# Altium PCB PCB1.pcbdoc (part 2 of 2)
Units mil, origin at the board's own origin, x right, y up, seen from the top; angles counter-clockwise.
Board outline 7352.2 x 4397.09 mil, 2 copper layers (Top Layer, Bottom Layer); 16 components, 5 nets, 164 pads, 4 vias.
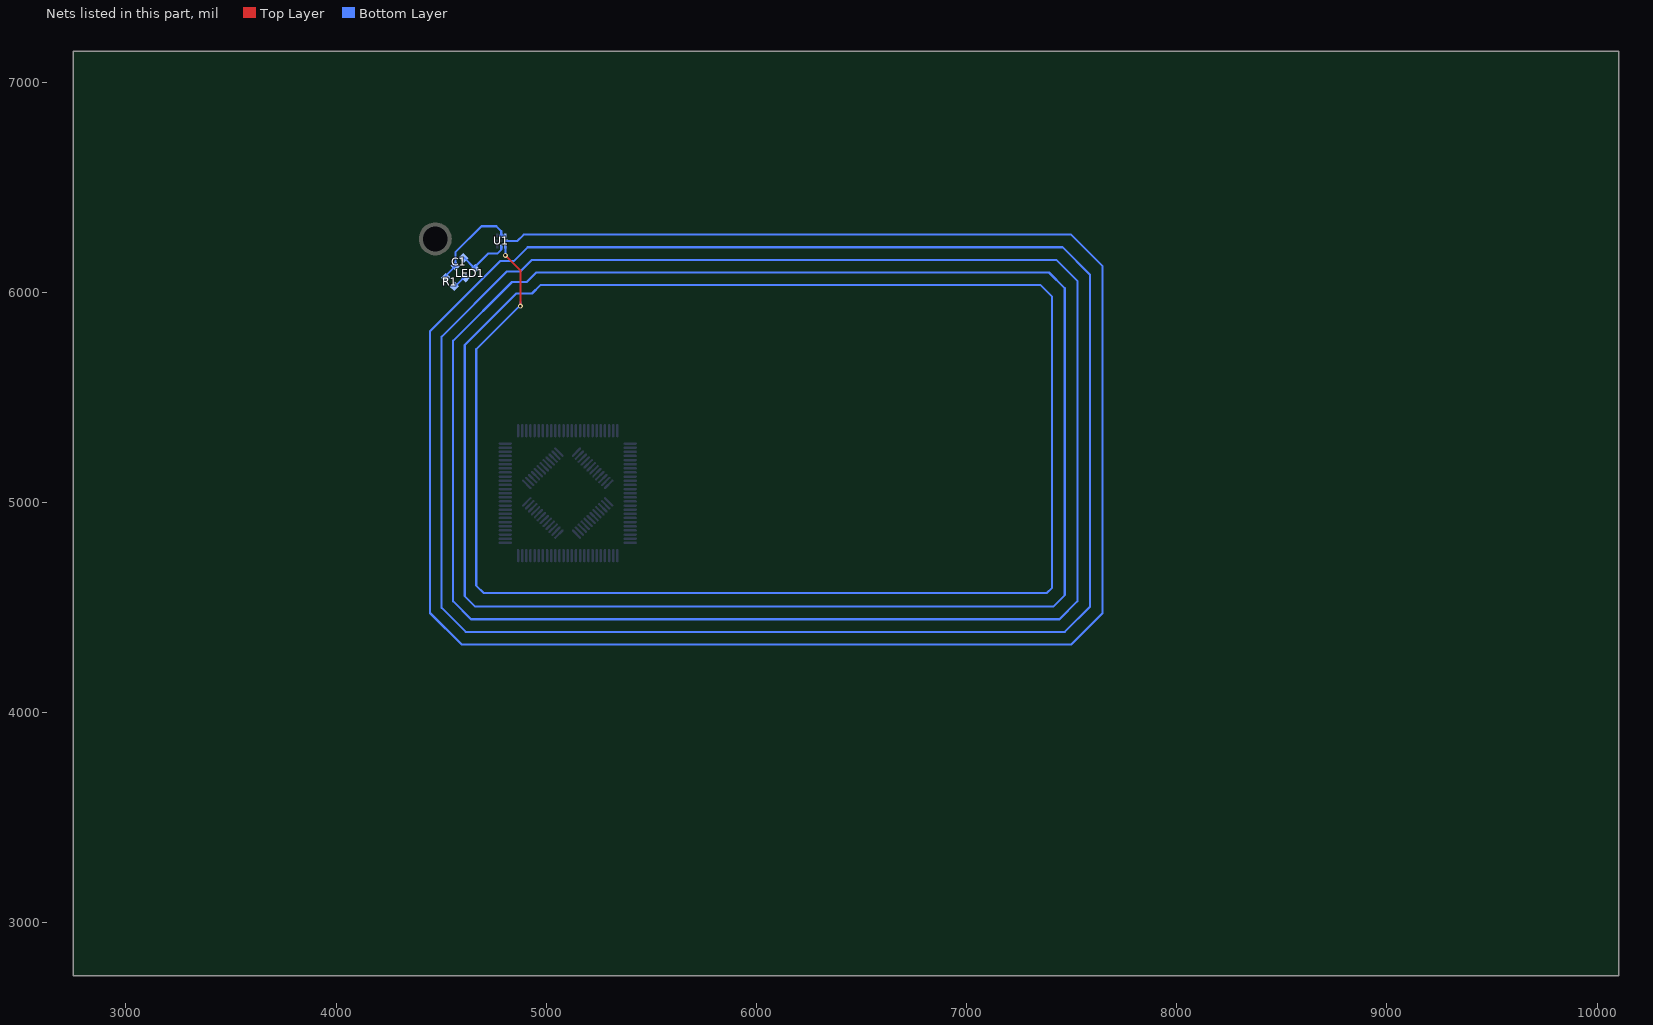
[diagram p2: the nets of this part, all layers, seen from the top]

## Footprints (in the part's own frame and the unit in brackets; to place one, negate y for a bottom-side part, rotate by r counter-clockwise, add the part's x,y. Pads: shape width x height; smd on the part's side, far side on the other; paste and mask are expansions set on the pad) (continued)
IMPORTED_IMAGE#5 [mil]
  Top Layer region: 1462.83,310 1462.05,279.15 1461.26,248.29 1511.13,247.91 1561,247.53 1561,266.2 1561,284.86 1540.2,295.77 1525.03,302.53 1517.76,303.46 1507.74,285.22 1501.83,276.56 1496.22,285.46 1489.8,295.65 1481.37,290.53 1472.94,285.42 1467.89,297.71 hole: 86000093.39,-55988379.52 86119717.09,-56015261.61 86119717.09,-56015261.61 86224717.48,-56038855.56 86224717.48,-56038855.56 86231250.4,-56029290.69 86231250.4,-56029290.69 86239350.75,-56042143.7 86239350.75,-56042143.7 86224717.48,-56038855.56 86224717.48,-56038855.56 86198036.54,-56077919.24 86198036.54,-56077919.24 86111917.99,-56167947.61 86111917.99,-56167947.61 86030375.85,-56214891.46 86030375.85,-56214891.46 85900348.8,-56257396.07 85900348.8,-56257396.07 85950221.09,-56122887.8 85950221.09,-56122887.8 86000093.39,-55988379.52 hole: 86523752.52,-56080432.1 86523752.52,-55927924.17 86523752.52,-55927924.17 86623497.12,-55988379.52 86623497.12,-55988379.52 86693941.74,-56058118.4 86693941.74,-56058118.4 86723241.72,-56140887.45 86723241.72,-56140887.45 86693941.74,-56205901.41 86693941.74,-56205901.41 86623497.12,-56232940.02 86623497.12,-56232940.02 86523752.52,-56232940.02 86523752.52,-56232940.02 86523752.52,-56080432.1
  Top Layer region: 187.89,305.72 193.32,273.62 198.74,241.52 202.45,264.66 206.17,287.8 197.03,296.76
  Top Layer region: 1230.67,305.11 1236.28,296.21 1241.89,287.31 1235.8,271.75 1232.64,265.71 1228.54,260.77 1224.03,257.42 1219.64,256.2 1209.57,256.2 1214.79,275.76 1220,295.33 1212.13,295.33 1208.84,293.34 1205.52,288.06 1202.42,280.48 1199.79,271.58 1197.87,262.37 1196.93,253.85 1197.2,246.99 1198.94,242.82 1202.08,241.63 1207.55,241.41 1214.6,242.12 1222.45,243.73 1241.82,248.7 1242.98,264.67 1244.13,280.65 1248.7,263.53 1254.48,251.44 1261.98,246.41 1270.71,246.41 1260.28,275.76 1249.84,305.11 1240.26,305.11
  Top Layer region: 640.42,278.21 636.1,300.22 634.74,273.32 633.38,246.41 683.25,246.41 733.12,246.41 731.76,273.32 730.41,300.22 726.08,278.21 721.76,256.2 712.48,256.2 703.2,256.2 701.84,278.21 700.48,300.22 696.16,278.21 691.84,256.2 682.56,256.2 673.28,256.2 672.12,273.32 670.96,290.44 666.4,273.32 660.67,261.23 653.29,256.2 644.74,256.2
  Top Layer region: 31.92,300.22 27.53,270.9 23.14,241.59 11.57,234.37 0,227.15 29.92,227.77 59.85,228.39 47.38,233.33 34.91,238.26 33.42,269.24
  Top Layer region: 415.52,300.22 414.73,278.21 413.94,256.2 404.7,256.2 400.75,257.55 396.83,261.23 393.39,266.67 390.89,273.32 386.33,290.44 385.17,268.42 384.02,246.41 403.97,246.41 423.91,246.41 424.7,258.64 425.49,270.87 430.52,258.64 435.55,246.41 454.67,246.41 473.79,246.41 473.79,265.4 473.79,284.39 463.38,290.7 452.96,297.01 439.41,285.98 425.85,274.94 420.68,287.58 hole: 75651591.53,-56086203.72 75651591.53,-55939467.42 75651591.53,-55939467.42 75751336.12,-55939467.42 75751336.12,-55939467.42 75851080.72,-55939467.42 75851080.72,-55939467.42 75851080.72,-56086203.72 75851080.72,-56086203.72 75851080.72,-56232940.02 75851080.72,-56232940.02 75751336.12,-56232940.02 75751336.12,-56232940.02 75651591.53,-56232940.02 75651591.53,-56232940.02 75651591.53,-56086203.72
  Top Layer region: 971.15,273.32 969.79,300.22 965.47,278.21 961.15,256.2 952.56,256.2 943.97,256.2 939.65,278.21 935.33,300.22 933.97,273.32 932.61,246.41 952.56,246.41 972.51,246.41
  Top Layer region: 1104.89,300.22 1103.54,273.32 1102.18,246.41 1129.93,246.41 1157.67,246.41 1159.74,270.87 1161.8,295.33 1150.28,295.33 1138.75,295.33 1145.31,288.89 1151.88,282.45 1140.77,269.32 1134.97,263.2 1129.71,259.14 1124.98,257.15 1120.78,257.22 1117.1,259.36 1113.95,263.58 1111.32,269.86 1109.22,278.21
  Top Layer region: 989.4,282.91 984.8,300.22 984.43,270.87 984.06,241.52 989.03,253.57 990.59,259.61 991.18,267.15 990.79,275.24
  Top Layer region: 831.51,273.32 830.15,300.22 825.83,278.21 821.51,256.2 812.92,256.2 804.33,256.2 800.01,278.21 795.69,300.22 794.33,273.32 792.97,246.41 812.92,246.41 832.87,246.41
  Top Layer region: 1832.63,300.22 1832.26,270.87 1831.89,241.52 1836.86,253.57 1838.42,259.61 1839.01,267.15 1838.62,275.24 1837.23,282.91
  Top Layer region: 237.12,300.22 235.76,273.32 234.4,246.41 254.35,246.41 274.3,246.41 272.94,273.32 271.58,300.22 267.26,278.21 262.94,256.2 254.35,256.2 245.76,256.2 241.44,278.21
  Top Layer region: 1902.85,300.22 1901.49,273.32 1900.13,246.41 1920.08,246.41 1940.03,246.41 1938.88,268.42 1937.72,290.44 1933.16,273.32 1927.42,261.23 1920.05,256.2 1911.5,256.2 1907.17,278.21
  Top Layer region: 173.19,273.32 171.84,300.22 167.51,278.21 163.19,256.2 154.6,256.2 146.02,256.2 141.69,278.21 137.37,300.22 136.01,273.32 134.66,246.41 154.6,246.41 174.55,246.41
  Top Layer region: 221.36,282.91 216.77,300.22 216.39,270.87 216.03,241.52 220.99,253.57 222.56,259.61 223.15,267.15 222.76,275.24
  Top Layer region: 1593.24,300.22 1592.87,270.87 1592.5,241.52 1597.47,253.57 1599.03,259.61 1599.63,267.15 1599.23,275.24 1597.84,282.91
  Top Layer region: 71.75,282.91 67.15,300.22 66.78,270.87 66.41,241.52 71.38,253.57 72.94,259.61 73.53,267.15 73.14,275.24
  Top Layer region: 1573.69,300.22 1573.49,261.09 1573.29,221.96 1577.83,238.96 1578.65,242.83 1579.25,247.31 1579.62,252.25 1579.76,257.47 1579.68,262.83 1579.36,268.16 1578.81,273.3 1578.03,278.09
  Top Layer region: 1321.47,299.38 1305.4,283.62 1289.33,267.86 1296.09,257.14 1299.87,252.97 1305.17,249.56 1311.29,247.26 1317.53,246.41 1332.22,246.41 1338.22,261.75 1344.21,277.08 1332.84,288.23 hole: 84313831.2,-55997799.99 84401287.26,-55944789.06 84401287.26,-55944789.06 84465073.93,-56007347.64 84465073.93,-56007347.64 84510122.33,-56075471.19 84510122.33,-56075471.19 84528860.6,-56151423.12 84528860.6,-56151423.12 84500588.15,-56212396.94 84500588.15,-56212396.94 84433042.2,-56230457.73 84433042.2,-56230457.73 84352129.85,-56206614.31 84352129.85,-56206614.31 84283758.2,-56141875.48 84283758.2,-56141875.48 84226375.13,-56050810.93 84226375.13,-56050810.93 84313831.2,-55997799.99
  Top Layer region: 1810.85,298.11 1796.53,286.46 1782.22,274.81 1775.75,285.07 1772.11,289.05 1766.97,292.31 1761.01,294.52 1754.92,295.33 1740.54,295.33 1740.54,285.85 1740.54,276.38 1755.5,282.01 1770.47,287.64 1770.47,277.86 1769.29,273.61 1766.07,269.29 1761.31,265.4 1755.5,262.44 1740.54,256.81 1740.54,241.83 1740.54,226.85 1762.99,227.54 1785.43,228.22 1767.01,235.33 1748.58,242.44 1766.13,256.66 1783.68,270.87 1787.88,258.64 1792.08,246.41 1808.7,247.19 1825.33,247.96 1812.86,252.89 1800.39,257.83 1800.39,271.69 1800.39,285.54 1812.03,285.54 1823.66,285.54 1817.25,291.83
  Top Layer region: 2026.72,291.83 2020.31,298.11 2005.7,286.22 1991.09,274.33 1996.17,261.35 2001.25,248.37 2035.45,248.37 2069.64,248.37 2064.52,256.5 2059.4,264.63 2061.64,265.98 2048.33,266.13 2041.89,266.94 2034.37,269.02 2026.71,272.07 2019.83,275.76 2004.87,285.24 2019,285.39 2033.13,285.54
  Top Layer region: 322.43,297.53 310.83,286.07 299.23,274.6 316.69,281.12 334.14,287.64 334.14,278.01 332.97,273.31 329.78,267.65 325.06,261.74 319.29,256.29 304.44,244.2 309.91,235.52 313.36,232.21 318.72,229.6 325.26,227.95 332.24,227.54 349.11,228.22 329.16,236.27 309.21,244.31 326.66,251.3 344.12,258.29 344.12,271.34 343.26,276.93 340.93,282.49 337.49,287.38 333.28,290.96
  Top Layer region: 908.11,285.19 893.59,297.01 883.18,290.7 872.77,284.39 874.36,253.17 875.96,221.96 880.03,254.34 884.09,286.73 895.89,282.89 907.68,279.04 913.98,250.5 920.28,221.96 921.46,247.66 922.64,273.37
  Top Layer region: 603.45,286.44 618.42,296.82 603.45,292.86 588.49,288.9 585.31,267.66 582.12,246.41 602.76,246.41 623.4,246.41 623.4,261.09 623.4,275.76 605.95,275.91 588.49,276.06
  Top Layer region: 124.68,296.76 107.23,293.5 89.77,290.24 86.58,268.32 83.4,246.41 104.04,246.41 124.68,246.41 124.68,271.59 hole: 72360019.85,-55939467.42 72360019.85,-56086203.72 72360019.85,-56086203.72 72360019.85,-56232940.02 72360019.85,-56232940.02 72260275.25,-56232940.02 72260275.25,-56232940.02 72160530.66,-56232940.02 72160530.66,-56232940.02 72160530.66,-56086203.72 72160530.66,-56086203.72 72160530.66,-55939467.42 72160530.66,-55939467.42 72260275.25,-55939467.42 72260275.25,-55939467.42 72360019.85,-55939467.42
  Top Layer region: 783,271.59 783,296.76 765.54,293.5 748.08,290.24 744.9,268.32 741.71,246.41 762.35,246.41 783,246.41 hole: 78743674.01,-56086203.72 78743674.01,-55939467.42 78743674.01,-55939467.42 78843418.61,-55939467.42 78843418.61,-55939467.42 78943163.2,-55939467.42 78943163.2,-55939467.42 78943163.2,-56086203.72 78943163.2,-56086203.72 78943163.2,-56232940.02 78943163.2,-56232940.02 78843418.61,-56232940.02 78843418.61,-56232940.02 78743674.01,-56232940.02 78743674.01,-56232940.02 78743674.01,-56086203.72
  Top Layer region: 1678.9,295.39 1669.82,289.89 1665.37,286.32 1662.52,282.04 1661.26,277.11 1661.56,271.61 1663.42,265.61 1666.83,259.19 1671.76,252.42 1678.2,245.37 1685.57,238.58 1692.73,232.94 1698.86,229.03 1703.14,227.43 1710.62,226.85 1710.62,255.15 1710.62,283.45 1694.76,289.42 hole: 88019921.47,-55988379.52 88119666.06,-55927924.17 88119666.06,-55927924.17 88119666.06,-56080432.1 88119666.06,-56080432.1 88119666.06,-56232940.02 88119666.06,-56232940.02 88019921.47,-56232940.02 88019921.47,-56232940.02 87949476.85,-56205901.41 87949476.85,-56205901.41 87920176.87,-56140887.45 87920176.87,-56140887.45 87949476.85,-56058118.4 87949476.85,-56058118.4 88019921.47,-55988379.52
  Top Layer region: 555.38,295.39 539.52,289.42 523.66,283.45 523.66,261.67 524.18,252.7 525.61,244.37 527.73,237.62 530.31,233.37 534.14,230.93 539.64,229.1 546.09,228.06 552.75,227.98 568.54,229.12 551.09,233.59 533.63,238.07 533.63,256.34 533.63,274.61 544.27,281.05 554.91,287.5 561.44,281.1 567.97,274.7 553.29,265.6 538.62,256.5 556.08,256.35 573.53,256.2 573.53,270.29 572.82,276.2 570.87,281.86 567.98,286.64 564.46,289.89
  Top Layer region: 2067.54,292.65 2059.45,295.33 2050.38,295.33 2056.12,280.65 2061.82,266.09 2069.7,270.87 2080,277.11 2074.26,286.22
  Top Layer region: 1644.51,295.18 1639.2,294.11 1633.03,291.1 1626.78,286.6 1621.21,281.08 1609.16,266.84 1615.59,256.63 1619.22,252.66 1624.36,249.41 1630.31,247.22 1636.4,246.41 1650.77,246.41 1650.77,261.09 1650.77,275.76 1638.31,275.91 1625.84,276.06 1640.8,285.54 1655.76,295.03
  Top Layer region: 1883.9,295.18 1878.58,294.11 1872.42,291.1 1866.17,286.6 1860.6,281.08 1848.54,266.84 1854.98,256.63 1858.61,252.66 1863.75,249.41 1869.7,247.22 1875.79,246.41 1890.16,246.41 1890.16,261.09 1890.16,275.76 1877.69,275.91 1865.22,276.06 1880.19,285.54 1895.15,295.03
  Top Layer region: 1994.89,294.73 1984.92,294.88 1979.95,294.25 1973.78,292.44 1967.21,289.73 1961.02,286.38 1947.1,277.74 1953.23,262.07 1959.35,246.41 1977.12,247.55 1994.89,248.68 1977.44,253.16 1965.11,258.84 1959.98,266.21 1961.36,270.33 1965.11,275.2 1970.66,280.21 1977.44,284.76
  Top Layer region: 1409.91,293.45 1406.35,293.65 1405.57,292.01 1405.29,289.24 1405.47,285.47 1406.11,280.86 1407.16,275.57 1408.61,269.73 1410.42,263.51 1412.58,257.04 1423.84,225.37 1431.45,233.44 1434.92,238.25 1438.75,245.38 1442.45,253.85 1445.59,262.72 1452.1,283.92 1431.74,278.7 1411.39,273.48 1411.39,286.03
  Top Layer region: 1356.4,292.51 1355.46,293.3 1354.6,293.07 1353.83,291.81 1353.16,289.54 1352.6,286.23 1352.15,281.9 1351.81,276.54 1351.61,270.15 1351.54,262.72 1351.54,226.85 1360.64,226.85 1369.75,226.85 1364.69,258.64 1363.38,266.5 1362.09,273.36 1360.85,279.21 1359.65,284.05 1358.5,287.88 1357.42,290.7
  Top Layer region: 1178.61,278.21 1173.57,290.44 1173.57,265.98 1173.57,241.52 1178.61,253.75 1180.16,259.46 1180.68,265.98 1180.16,272.49
  Top Layer region: 1057.29,290.44 1054.1,268.42 1050.92,246.41 1072.25,246.41 1093.59,246.41 1090.4,268.42 1087.22,290.44 1072.25,290.44
  Top Layer region: 1031.24,281.33 1020.15,288.05 1011.45,274.57 1008.06,268.56 1005.3,262.17 1003.43,256.17 1002.74,251.31 1002.74,241.52 1012.56,256.2 1022.38,270.87 1032.2,256.2 1042.03,241.52 1042.18,258.07 1042.33,274.61
  Top Layer region: 354.09,285.54 354.09,265.98 354.09,246.41 364.07,246.41 374.04,246.41 374.04,265.98 374.04,285.54 364.07,285.54
  Top Layer region: 510.98,262.11 504.96,268.02 491.87,262.88 478.77,257.74 497.89,256.97 517.01,256.2
  Top Layer region: 2061.82,266.09 2061.64,265.98 2061.86,265.98
  Top Layer region: 366.43,192.61 365.25,166.39 364.07,140.17 341.63,136.97 319.18,133.76 307.98,147.9 296.77,162.03 289.62,139.93 282.47,117.83 288.44,94.51 294.41,71.19 330.22,64.6 366.04,58.01 352.59,49.65 339.13,41.28 351.6,41.13 364.07,40.98 364.07,21.42 364.07,1.85 374.04,1.85 384.02,1.85 384.02,14.14 384.02,26.43 413.94,39.42 443.86,52.41 443.86,61.95 443.86,71.48 434.25,65.66 424.64,59.84 404.33,79.76 384.02,99.68 396.48,99.83 408.95,99.98 393.99,110.46 379.03,120.94 401.46,116.12 423.89,111.3 429.06,119.5 434.23,127.69 406.68,130.8 379.12,133.92 372.78,163.26 hole: 74160120.55,-57602478.83 74161766.34,-57455742.53 74161766.34,-57455742.53 74308211.36,-57645629.08 74308211.36,-57645629.08 74454656.37,-57835525.42 74454656.37,-57835525.42 74454656.37,-57670085.13 74454656.37,-57670085.13 74454656.37,-57504654.63 74454656.37,-57504654.63 74598388.33,-57504654.63 74598388.33,-57504654.63 74659810.59,-57513565.8 74659810.59,-57513565.8 74720803.63,-57537829.26 74720803.63,-57537829.26 74774313.96,-57573739.91 74774313.96,-57573739.91 74813288.07,-57617592.67 74813288.07,-57617592.67 74884455.84,-57730530.71 74884455.84,-57730530.71 74769300.7,-57660733.14 74769300.7,-57660733.14 74654145.56,-57590935.57 74654145.56,-57590935.57 74654145.56,-57694531.4 74654145.56,-57694531.4 74654145.56,-57798127.23 74654145.56,-57798127.23 74778826.31,-57799623.94 74778826.31,-57799623.94 74903507.05,-57801120.65 74903507.05,-57801120.65 74767535.22,-57885611.41 74767535.22,-57885611.41 74631573.36,-57970092.39 74631573.36,-57970092.39 74767535.22,-58023122.89 74767535.22,-58023122.89 74903507.05,-58076153.39 74903507.05,-58076153.39 74753890.16,-58076153.39 74753890.16,-58076153.39 74688900.41,-58073906.24 74688900.41,-58073906.24 74626699.2,-58067270.61 74626699.2,-58067270.61 74567485.54,-58056405.25 74567485.54,-58056405.25 74511458.43,-58041468.9 74511458.43,-58041468.9 74458816.86,-58022620.32 74458816.86,-58022620.32 74409759.85,-58000018.23 74409759.85,-58000018.23 74364486.39,-57973821.39 74364486.39,-57973821.39 74323195.49,-57944188.54 74323195.49,-57944188.54 74286086.14,-57911278.43 74286086.14,-57911278.43 74253357.36,-57875249.81 74253357.36,-57875249.81 74225208.14,-57836261.4 74225208.14,-57836261.4 74201837.48,-57794471.97 74201837.48,-57794471.97 74183444.4,-57750040.25 74183444.4,-57750040.25 74170227.88,-57703124.99 74170227.88,-57703124.99 74162386.93,-57653884.94 74162386.93,-57653884.94 74160120.55,-57602478.83
  Top Layer region: 563.56,143.7 563.56,187.72 553.58,187.72 543.61,187.72 543.61,148.59 543.61,109.46 524.82,109.46 506.04,109.46 500.37,88.2 498.33,78.84 497.63,70.96 498.32,64.49 500.45,59.36 504.06,55.49 509.2,52.82 515.91,51.27 524.25,50.77 543.61,50.77 543.61,31.2 543.61,11.64 558.26,11.64 572.91,11.64 567.68,24.98 562.46,38.32 592.93,44.3 623.4,50.28 623.4,63.24 622.47,70.08 619.83,76.68 615.72,82.84 610.37,88.35 604.04,92.99 596.96,96.57 589.37,98.87 581.51,99.68 563.56,99.68 hole: 76848526.68,-58083451.08 76848526.68,-57879644.14 76848526.68,-57879644.14 76973207.43,-57920358.57 76973207.43,-57920358.57 77024163.36,-57949035.28 77024163.36,-57949035.28 77070736.45,-57997019.73 77070736.45,-57997019.73 77107777.07,-58057625.33 77107777.07,-58057625.33 77130135.6,-58124165.51 77130135.6,-58124165.51 77162383.03,-58287248.23 77162383.03,-58287248.23 77005454.86,-58287248.23 77005454.86,-58287248.23 76848526.68,-58287248.23 76848526.68,-58287248.23 76848526.68,-58083451.08 hole: 76649037.49,-57895951.43 76649037.49,-58042687.73 76649037.49,-58042687.73 76643744.4,-58094666.87 76643744.4,-58094666.87 76628811.78,-58135700.97 76628811.78,-58135700.97 76605659.58,-58165292.62 76605659.58,-58165292.62 76575707.76,-58182944.4 76575707.76,-58182944.4 76540376.27,-58188158.91 76540376.27,-58188158.91 76501085.08,-58180438.73 76501085.08,-58180438.73 76459254.15,-58159286.44 76459254.15,-58159286.44 76416303.42,-58124204.64 76416303.42,-58124204.64 76358965.4,-58041055.29 76358965.4,-58041055.29 76356410.53,-57967869.34 76356410.53,-57967869.34 76404581.41,-57915787.73 76404581.41,-57915787.73 76499420.6,-57895951.43 76499420.6,-57895951.43 76649037.49,-57895951.43
  Top Layer region: 1189.87,102.1 1192.79,177.89 1165.52,165.71 1138.26,153.53 1155.13,150.34 1172,147.16 1172,94.65 1172,42.14 1162.71,36.51 1153.43,30.88 1146.47,41.92 1139.52,52.95 1151.97,60.5 1164.42,68.04 1145.77,78.67 1127.11,89.3 1144.57,89.6 1162.02,89.9 1162.02,99.68 1162.02,109.46 1147.06,109.46 1132.1,109.46 1130.94,136.36 1129.79,163.26 1124.8,143.7 1121.98,135.52 1117.96,127.73 1113.29,121.19 1108.5,116.8 1097.19,109.46 1112.15,98.93 1127.11,88.41 1113.52,83.08 1099.92,77.74 1113.23,69.68 1126.54,61.61 1120.01,55.21 1113.48,48.81 1102.84,55.26 1092.2,61.7 1092.2,84.94 1092,90.13 1091.44,95.95 1090.54,102.22 1089.35,108.73 1087.9,115.29 1086.25,121.7 1084.43,127.76 1082.48,133.28 1072.75,158.37 1061.96,158.37 1051.17,158.37 1066.7,136.63 1082.23,114.89 1082.23,78.22 1082.23,41.54 1114.65,32.19 1121.56,30.34 1128.81,28.69 1136.16,27.26 1143.4,26.09 1150.32,25.2 1156.71,24.63 1162.34,24.41 1167.01,24.57 1186.96,26.31
  Top Layer region: 1511.13,138.5 1511.13,177.32 1494.18,170.94 1477.23,164.56 1489.19,160.65 1501.16,156.74 1501.16,132.44 1501.16,108.13 1468.74,130.1 1436.32,152.06 1457.28,128.32 1466.06,118 1474.46,107.46 1481.55,97.95 1486.35,90.68 1494.45,76.79 1477.86,83.04 1461.26,89.28 1461.26,78.89 1461.26,68.5 1481.21,63.38 1501.16,58.27 1501.16,34.95 1501.16,11.64 1511.13,11.64 1521.11,11.64 1521.11,31.2 1521.11,50.77 1536.07,50.77 1551.03,50.77 1551.03,60.55 1551.03,70.33 1535.72,70.33 1520.4,70.33 1531.36,90.42 1534.22,94.84 1538.13,99.72 1542.93,104.89 1548.44,110.19 1554.49,115.46 1560.9,120.55 1567.5,125.28 1574.11,129.51 1605.89,148.52 1584.84,148.55 1563.8,148.59 1545.07,124.13 1537.2,114.64 1529.61,106.86 1523.17,101.61 1518.74,99.68 1511.13,99.68
  Top Layer region: 1785.7,167.73 1779.8,177.08 1762.67,170.9 1758.75,169.17 1754.19,166.61 1749.14,163.35 1743.78,159.5 1738.26,155.2 1732.75,150.56 1727.42,145.71 1722.42,140.78 1699.32,116.83 1670.16,144.23 1641.01,171.62 1634.76,165.5 1628.52,159.38 1657.1,134.73 1685.68,110.08 1668.23,109.77 1650.77,109.46 1650.77,94.79 1650.77,80.11 1670.72,80.11 1690.67,80.11 1690.67,47.51 1691.26,34.26 1692.87,22.29 1695.25,12.91 1698.15,7.45 1705.63,0 1708.7,34.64 1711.76,69.29 1726.15,63.87 1740.54,58.45 1740.54,68.94 1740.09,71.28 1738.81,73.92 1736.77,76.77 1734.08,79.74 1730.82,82.73 1727.08,85.66 1722.95,88.44 1718.53,90.98 1696.52,102.53 1730.62,130.45 1744.93,141.29 1758.65,150.17 1770.25,156.17 1778.16,158.37 1791.59,158.37
  Top Layer region: 701.15,173.05 696.45,145.38 691.75,117.7 677.53,123.06 663.3,128.41 663.3,120.45 663.71,118.49 664.88,115.96 666.72,112.98 669.16,109.63 672.12,106.03 675.5,102.29 679.24,98.51 683.25,94.79 691,87.21 697.34,79.68 701.63,73.07 703.2,68.24 703.2,59.39 692.23,66.04 681.26,72.69 692.63,51.86 704,31.02 728.53,37.06 753.07,43.1 753.07,27.37 753.13,23.86 753.33,20.82 753.69,18.26 754.24,16.17 754.99,14.57 755.96,13.44 757.19,12.79 758.69,12.63 760.49,12.95 762.6,13.75 765.06,15.03 767.88,16.8 771.08,19.06 774.69,21.8 778.74,25.03 783.23,28.76 803.65,45.87 780.85,52.24 758.06,58.6 785.84,59.57 813.62,60.55 802.94,80.11 792.27,99.68 770.18,100.81 748.08,101.95 763.6,106.06 779.12,110.16 796.58,139.16 814.05,168.15 779.64,168.15 745.23,168.15 738.64,151.31 732.05,134.47 722.76,148.86 713.48,163.26 713.33,146.84 714.4,139.36 717.43,131.12 721.95,123.13 727.49,116.38 741.81,102.33 730.07,90.82 718.33,79.3 729.61,72.37 740.89,65.44 727.03,52.83 713.17,40.21 712.02,47.93 711.53,50.98 710.91,54.38 710.14,58.19 709.22,62.44 708.13,67.2 706.86,72.51 705.41,78.43 703.75,85 703.25,87.77 702.78,91.89 702.35,97.17 701.98,103.41 701.67,110.4 701.43,117.95 701.27,125.86 701.21,133.92 hole: 79042907.8,-57196841 79042907.8,-57301835.71 79042907.8,-57301835.71 79042907.8,-57406830.43 79042907.8,-57406830.43 78868354.76,-57408327.14 78868354.76,-57408327.14 78693801.71,-57409823.85 78693801.71,-57409823.85 78843418.61,-57504654.63 78843418.61,-57504654.63 78993035.5,-57599485.41 78993035.5,-57599485.41 78811171.18,-57600982.12 78811171.18,-57600982.12 78629306.86,-57602478.83 78629306.86,-57602478.83 78662701.35,-57432411.46 78662701.35,-57432411.46 78696095.84,-57262344.09 78696095.84,-57262344.09 78869501.82,-57229592.54 78869501.82,-57229592.54 79042907.8,-57196841
  Top Layer region: 1897.83,172.06 1891.77,172.24 1884.27,170.74 1875.2,167.62 1855.25,159.75 1872.7,159.06 1890.16,158.37 1890.16,140.5 1890.16,122.63 1857.74,125.57 1825.33,128.52 1857.17,117.74 1889.01,106.96 1894.35,93.31 1899.69,79.66 1879.96,90.01 1860.24,100.37 1860.24,91.05 1861.22,87.1 1863.9,83.22 1867.86,79.85 1872.7,77.45 1879.33,75.77 1888.16,74.37 1898.03,73.38 1907.8,72.97 1930.43,72.78 1919.05,86.23 1907.67,99.68 1933.82,99.68 1959.98,99.68 1959.98,109.46 1959.98,119.24 1935.05,119.24 1910.11,119.24 1910.11,143.12 1909.69,152.9 1908.36,160.6 1906.01,166.31 1902.54,170.1
  Top Layer region: 1367.62,170.01 1356.02,154.46 1344.43,138.91 1313.2,154.19 1281.97,169.46 1272.81,163.91 1263.64,158.35 1269.42,136.35 1275.2,114.35 1258.27,127.97 1241.34,141.6 1235.62,135.99 1229.9,130.38 1250.82,117.57 1271.74,104.75 1271.74,91.86 1271.74,78.96 1262.46,84.59 1253.17,90.21 1247.35,80.98 1241.53,71.74 1261.62,65.48 1281.72,59.23 1281.72,33.8 1281.72,8.38 1288.49,15.01 1295.26,21.65 1293.47,85.12 1291.69,148.59 1301.08,148.59 1305.3,147.67 1309.86,145.17 1314.21,141.46 1317.81,136.94 1325.15,125.29 1313.41,121.45 1305.12,116 1301.67,108.3 1301.67,98.99 1321.62,109.46 1341.56,119.93 1341.56,109.8 1338.46,102.65 1331,99.68 1320.44,99.68 1326.08,90.73 1331.72,81.78 1319.18,76.06 1306.65,70.33 1319.12,64.62 1331.59,58.92 1331.59,35.28 1331.59,11.64 1341.56,11.64 1351.54,11.64 1351.54,31.2 1351.54,50.77 1363.06,50.77 1374.58,50.77 1356.53,70.33 1338.47,89.9 1350.18,89.9 1361.89,89.9 1356.23,112.03 1350.57,134.16 1383.47,147.72 1416.37,161.28 1392,165.65
  Top Layer region: 255.02,157.96 243.08,165.2 218.79,160.65 194.5,156.09 194.5,142.9 194.5,129.71 176.97,120.51 159.44,111.31 135.97,129.95 125.96,137.16 116.05,143 107.4,146.88 101.13,148.2 89.77,147.81 117.2,133.21 144.63,118.62 144.63,103.68 144.63,88.74 135.34,94.37 126.06,100 119.79,90.06 113.53,80.11 134.07,80.11 154.6,80.11 154.6,71.82 154.6,63.53 184.35,62.7 214.1,61.87 219.85,70.99 225.6,80.11 205.65,80.11 197.49,80.77 190.02,82.57 184.06,85.23 180.44,88.47 175.17,96.83 197.3,116.7 202.23,120.83 207.77,124.97 213.73,129 219.92,132.81 226.14,136.29 232.23,139.33 237.97,141.82 243.2,143.64 266.96,150.73
  Top Layer region: 947.58,159.91 892.69,163.26 892.7,156.99 894.64,154.07 899.92,150.78 907.72,147.51 917.25,144.67 941.79,138.63 959.64,114.57 962.49,111.07 962.55,111.1 962.52,111.03 962.49,111.07 950.7,107.22 945.78,104.8 941.17,101.07 937.37,96.55 934.9,91.73 930.95,80.11 940.69,80.11 944.95,81.34 949.35,84.66 953.37,89.59 956.49,95.6 962.52,111.03 967.26,105.2 974.79,97.49 981.37,92.22 986.12,90.2 994.75,89.9 978.41,114.35 962.08,138.81 976.68,138.81 982.79,139.51 988.63,141.41 993.55,144.24 996.87,147.68 1002.47,156.56
  Top Layer region: 853.11,158.37 872.87,126.58 892.64,94.79 892.68,73.37 892.71,51.95 930.12,48.11 945.19,46.49 958.56,44.92 968.79,43.57 974.41,42.63 980.93,44.09 986.92,49.9 992.54,58.81 952.66,65.42 912.77,72.03 906.73,81.61 900.69,91.2 919.13,104.42 937.57,117.64 930.34,124.73 923.12,131.81 909.48,120.71 895.85,109.61 884.52,133.99 873.19,158.37 863.15,158.37
  Top Layer region: 822.89,135.11 822.89,150.99 807.93,138.81 797.36,129.12 792.97,122.94 794.15,121.5 797.36,120.33 802.12,119.53 807.93,119.24 822.89,119.24
  Top Layer region: 1834.33,88.2 1823.38,102.64 1816.24,91.3 1809.09,79.95 1854.19,60.99 1899.3,42.03 1912.09,21.94 1917.66,14.14 1923.35,7.75 1928.51,3.44 1932.46,1.85 1936.16,2.62 1938.57,4.72 1939.74,7.82 1939.71,11.6 1938.54,15.75 1936.27,19.94 1932.95,23.86 1928.63,27.17 1917.24,34.08 1943.6,47.63 1953.83,53.63 1962.21,59.98 1967.88,65.9 1969.96,70.64 1969.96,80.11 1954.99,80.11 1940.03,80.11 1940.03,65.44 1940.03,50.77 1926.56,50.77 1915.91,51.78 1903.21,54.56 1889.36,58.77 1875.26,64.02 1861.81,69.95 1849.91,76.2 1840.45,82.41
  Top Layer region: 161.06,49.18 146.29,50.22 137.54,47.72 134.66,41.66 134.66,32.56 157.1,28.32 166.8,26.57 176.61,24.94 185.4,23.6 192.01,22.75 204.48,21.42 204.48,30.06 202.71,33.88 197.88,37.9 190.75,41.63 182.03,44.6
  Top Layer region: 319.08,48.5 313.96,50.01 304.72,46.18 293.92,39.63 300.32,29.48 306.71,19.33 314.9,32.32 319.57,42.37
  Top Layer region: 962.55,42.62 950.7,38.74 945.78,36.32 941.17,32.6 937.37,28.07 934.9,23.25 930.95,11.64 940.69,11.64 944.95,12.86 949.35,16.19 953.37,21.11 956.49,27.13
  Top Layer region: 1865.22,31.2 1871.39,40.98 1860.83,40.98 1853.37,38.11 1850.26,31.2 1851.55,24.29 1854.66,21.42 1859.58,24.29
  Top Layer region: 1568.05,38.28 1561,40.98 1551.03,40.98 1551.03,25.73 1551.03,10.48 1561,16.53 1568.05,23.5 1570.98,31.78
  Top Layer region: 1880.19,32.36 1880.19,22 1883.12,14.68 1890.16,11.64 1897.2,12.9 1900.13,15.95 1897.2,20.77 1890.16,26.31
IMPORTED_IMAGE#6 [mil]
  Top Layer region: 203 vertices and 22 holes, not listed, extent 0,0 1398.38,350.15
LED_0603 [mil]
  rect 31.5x31.5 smd: 1(-33.5,-0.4) 2(29.5,-0.2)
  silkscreen extent -61,-30 53,29
LQFP-48_L7.0-W7.0-P0.50-LS9.0-BL [mm]
  oval 0.27x1.5 smd: 1(-2.75,-4.25) 2(-2.25,-4.25) 3(-1.75,-4.25) 4(-1.25,-4.25) 5(-0.75,-4.25) 6(-0.25,-4.25) 7(0.25,-4.25) 8(0.75,-4.25) 9(1.25,-4.25) 10(1.75,-4.25) 11(2.25,-4.25) 12(2.75,-4.25) 25(2.75,4.25) 26(2.25,4.25) 27(1.75,4.25) 28(1.25,4.25) 29(0.75,4.25) 30(0.25,4.25) 31(-0.25,4.25) 32(-0.75,4.25) 33(-1.25,4.25) 34(-1.75,4.25) 35(-2.25,4.25) 36(-2.75,4.25)
  oval 1.5x0.27 smd: 13(4.25,-2.75) 14(4.25,-2.25) 15(4.25,-1.75) 16(4.25,-1.25) 17(4.25,-0.75) 18(4.25,-0.25) 19(4.25,0.25) 20(4.25,0.75) 21(4.25,1.25) 22(4.25,1.75) 23(4.25,2.25) 24(4.25,2.75) 37(-4.25,2.75) 38(-4.25,2.25) 39(-4.25,1.75) 40(-4.25,1.25) 41(-4.25,0.75) 42(-4.25,0.25) 43(-4.25,-0.25) 44(-4.25,-0.75) 45(-4.25,-1.25) 46(-4.25,-1.75) 47(-4.25,-2.25) 48(-4.25,-2.75)
  silkscreen extent -3.59,-4.46 3.3,3.34
LQFP-100_L14.0-W14.0-P0.50-LS16.0-BL [mm]
  oval 0.3x1.6 smd: 1(-6,-7.55) 2(-5.5,-7.55) 3(-5,-7.55) 4(-4.5,-7.55) 5(-4,-7.55) 6(-3.5,-7.55) 7(-3,-7.55) 8(-2.5,-7.55) 9(-2,-7.55) 10(-1.5,-7.55) 11(-1,-7.55) 12(-0.5,-7.55) 13(0,-7.55) 14(0.5,-7.55) 15(1,-7.55) 16(1.5,-7.55) 17(2,-7.55) 18(2.5,-7.55) 19(3,-7.55) 20(3.5,-7.55) 21(4,-7.55) 22(4.5,-7.55) 23(5,-7.55) 24(5.5,-7.55) 25(6,-7.55) 51(6,7.55) 52(5.5,7.55) 53(5,7.55) 54(4.5,7.55) 55(4,7.55) 56(3.5,7.55) 57(3,7.55) 58(2.5,7.55) 59(2,7.55) 60(1.5,7.55) 61(1,7.55) 62(0.5,7.55) 63(0,7.55) 64(-0.5,7.55) 65(-1,7.55) 66(-1.5,7.55) 67(-2,7.55) 68(-2.5,7.55) 69(-3,7.55) 70(-3.5,7.55) 71(-4,7.55) 72(-4.5,7.55) 73(-5,7.55) 74(-5.5,7.55) 75(-6,7.55)
  oval 1.6x0.3 smd: 26(7.55,-6) 27(7.55,-5.5) 28(7.55,-5) 29(7.55,-4.5) 30(7.55,-4) 31(7.55,-3.5) 32(7.55,-3) 33(7.55,-2.5) 34(7.55,-2) 35(7.55,-1.5) 36(7.55,-1) 37(7.55,-0.5) 38(7.55,0) 39(7.55,0.5) 40(7.55,1) 41(7.55,1.5) 42(7.55,2) 43(7.55,2.5) 44(7.55,3) 45(7.55,3.5) 46(7.55,4) 47(7.55,4.5) 48(7.55,5) 49(7.55,5.5) 50(7.55,6) 76(-7.55,6) 77(-7.55,5.5) 78(-7.55,5) 79(-7.55,4.5) 80(-7.55,4) 81(-7.55,3.5) 82(-7.55,3) 83(-7.55,2.5) 84(-7.55,2) 85(-7.55,1.5) 86(-7.55,1) 87(-7.55,0.5) 88(-7.55,0) 89(-7.55,-0.5) 90(-7.55,-1) 91(-7.55,-1.5) 92(-7.55,-2) 93(-7.55,-2.5) 94(-7.55,-3) 95(-7.55,-3.5) 96(-7.55,-4) 97(-7.55,-4.5) 98(-7.55,-5) 99(-7.55,-5.5) 100(-7.55,-6)
  silkscreen extent -7.03,-8 6.25,6.25
R0603 [mil]
  rect 31.75x34.02 smd: 1(-29.66,0) 2(29.66,0)
  silkscreen extent -55,-26 55,26
XQFN-8_L1.6-W1.6-P0.50-BR [mm]
  rect 0.5x0.3 smd: 1(0.65,-0.5) 2(0.65,0) 3(0.65,0.5) 5(-0.65,0.5) 6(-0.65,0) 7(-0.65,-0.5)
  rect 0.3x0.5 smd: 4(0,0.6) 8(0,-0.6)
  rect 0.3x0.3 smd: 9(0,0)
  silkscreen extent -1,-1 1.33,1

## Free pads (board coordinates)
  round 157.48 hole 118.11: 4(4472.01,6255.08)

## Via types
v1: diameter 24.02, hole 12.01, Top Layer to Bottom Layer, 4 vias

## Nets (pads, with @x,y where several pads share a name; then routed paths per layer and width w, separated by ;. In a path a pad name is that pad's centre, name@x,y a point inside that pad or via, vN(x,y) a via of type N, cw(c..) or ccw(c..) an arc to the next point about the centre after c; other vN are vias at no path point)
$1N308: U1.1 U1.8 | length 45132.8
  Top Layer w10: v1(4805.31,6176.78) 4877.01,6105.08 v1@4877.01,5940.08
  Bottom Layer w10: U1.8@4804.25,6245.08 4862.01,6245.08 4892.01,6275.08 7497.01,6275.08 7647.01,6125.08 7647.01,4475.08 7497.01,4325.08 4597.01,4325.08 4447.01,4475.08 4447.01,5815.08 4782.01,6150.08 4847.01,6150.08 4912.01,6215.08 7457.01,6215.08 7587.01,6085.08 7587.01,4505.08 7467.01,4385.08 4617.01,4385.08 4502.01,4500.08 4502.01,5790.08 4812.01,6100.08 4877.01,6100.08 4932.01,6155.08 7427.01,6155.08 7527.01,6055.08 7527.01,4530.08 7442.01,4445.08 4642.01,4445.08 4557.01,4530.08 4557.01,5770.08 4837.01,6050.08 4907.01,6050.08 4952.01,6095.08 7392.01,6095.08 7467.01,6020.08 7467.01,4560.08 7412.01,4505.08 4662.01,4505.08 4612.01,4555.08 4612.01,5750.08 4857.01,5995.08 4932.01,5995.08 4972.01,6035.08 7352.01,6035.08 7407.01,5980.08 7407.01,4595.08 7382.01,4570.08 4702.01,4570.08 4667.01,4605.08 4667.01,5730.08 4872.01,5935.08 v1(4877.01,5935.08) 4877.01,5955.08 ; U1.1@4805.31,6219.49 v1(4805.31,6176.78) v1@4807.01,6175.08
$1N540: LED1.2 R1.2 | length 64.9
  Bottom Layer w10: R1.2@4562.98,6034.11 4571.32,6034.11 LED1.2@4611.29,6074.08
GND: C1.1 LED1.1 U1.2 | length 256.4
  Bottom Layer w10: C1.1@4606.5,6164.57 4609.9,6164.57 LED1.1@4655.98,6118.48 ; LED1.1@4660.98,6113.48 LED1.1@4655.98,6118.48 ; U1.2@4785.63,6219.49 4785.63,6203.7 4767.01,6185.08 4722.57,6185.08 LED1.1@4655.98,6118.48
VCC: C1.2 R1.1 U1.6 U1.7 | length 456.6
  Bottom Layer w10: R1.1@4521.04,6076.05 4521.04,6079.11 4562.52,6120.59 C1.2@4562.52,6130.59 ; C1.2@4567.52,6125.59 4567.52,6190.59 4692.01,6315.08 4762.01,6315.08 4785.63,6291.46 U1.6@4785.63,6270.67 ; U1.6@4780.63,6270.67 U1.6@4785.63,6270.67 ; U1.7@4800.31,6270.67 U1.6@4785.63,6270.67
"": 
pads on no net: U1.3 U1.4 U1.5 U1.9 U2.1 U2.2 U2.3 U2.4 U2.5 U2.6 U2.7 U2.8 U2.9 U2.10 U2.11 U2.12 U2.13 U2.14 U2.15 U2.16 U2.17 U2.18 U2.19 U2.20 U2.21 U2.22 U2.23 U2.24 U2.25 U2.26 U2.27 U2.28 U2.29 U2.30 U2.31 U2.32 U2.33 U2.34 U2.35 U2.36 U2.37 U2.38 U2.39 U2.40 U2.41 U2.42 U2.43 U2.44 U2.45 U2.46 U2.47 U2.48 U3.1 U3.2 U3.3 U3.4 U3.5 U3.6 U3.7 U3.8 U3.9 U3.10 U3.11 U3.12 U3.13 U3.14 U3.15 U3.16 U3.17 U3.18 U3.19 U3.20 U3.21 U3.22 U3.23 U3.24 U3.25 U3.26 U3.27 U3.28 U3.29 U3.30 U3.31 U3.32 U3.33 U3.34 U3.35 U3.36 U3.37 U3.38 U3.39 U3.40 U3.41 U3.42 U3.43 U3.44 U3.45 U3.46 U3.47 U3.48 U3.49 U3.50 U3.51 U3.52 U3.53 U3.54 U3.55 U3.56 U3.57 U3.58 U3.59 U3.60 U3.61 U3.62 U3.63 U3.64 U3.65 U3.66 U3.67 U3.68 U3.69 U3.70 U3.71 U3.72 U3.73 U3.74 U3.75 U3.76 U3.77 U3.78 U3.79 U3.80 U3.81 U3.82 U3.83 U3.84 U3.85 U3.86 U3.87 U3.88 U3.89 U3.90 U3.91 U3.92 U3.93 U3.94 U3.95 U3.96 U3.97 U3.98 U3.99 U3.100
copper on no net: | length 21166.7
  Top Layer w10: 5247.01,4795.08 5632.01,4795.08 5632.01,5265.08 5622.01,5265.08 ; 5477.01,5755.08 5877.01,5755.08 ; 5632.01,4954.37 5856.3,4954.37 5857.01,4955.08 ; 5632.01,5105.08 5847.01,5105.08 ; 5637.01,4795.08 5852.01,4795.08 ; 6087.01,4605.08 6087.01,5065.08 6497.01,5065.08 6497.01,4825.08 6212.01,4825.08 6212.01,4590.08 ; 6147.01,5450.08 6147.01,5215.08 6162.01,5215.08 ; 6212.01,4830.08 6212.01,5065.08 ; 6417.01,5455.08 6417.01,5700.08 ; 6452.01,4550.08 6452.01,4820.08 ; 6452.01,4775.08 6902.01,4775.08 6902.01,4499.45 ; 6497.01,4980.08 6857.01,4980.08 ; 6497.01,5050.08 6497.01,5215.08 ; 6497.01,5066.22 6647.01,5065.08 ; 6497.01,5115.08 6647.01,5115.08 ; 6627.01,4975.08 6627.01,4777.58 6629.51,4775.08 ; 6687.01,4530.08 6687.01,4775.08 ; 6831.87,5089.94 6857.01,5089.94 ; 6857.01,4777.47 6857.01,4980.08 ; 6857.01,4910.08 7249.53,4910.08 7262,4897.61 ; 6857.01,5215.08 6857.01,4980.08
  Top Layer w15.75: 5232.01,5265.08 5852.01,5265.08 5857.01,5270.08 ; 5469.51,5462.58 5477.01,5470.08 5477.01,5875.08 ; 5857.01,5215.08 6512.01,5215.08 ; 5877.01,5455.08 5877.01,6010.08 ; 6114.51,5457.58 6122.01,5465.08 6122.01,6015.08 ; 6512.01,5445.08 6512.01,5215.08 ; 7102.3,5217.1 7100.27,5215.08 6512.01,5215.08
  Top Layer w23.62: 5217.01,5460.08 7012.01,5455.08 ; 5232.01,6010.08 5237.01,4705.08 7292.01,4445.08 7317.01,4445.08 7331.45,4471.86 7322.01,4700.08 7262,4897.61 7102.3,5232.1 6902.01,5640.08 6658.23,6012.93 ; 5232.01,6015.08 6657.01,6015.08 ; 5852.01,5455.08 5857.01,4630.08 ; 5857.01,5230.08 5897.01,5230.08 ; 5877.01,4595.08 5877.01,4625.08 ; 5897.01,5455.08 5902.01,4625.08 ; 5952.01,6045.08 5954.51,6015.08
  other v1: 3492.01,5690.08 3012.01,6885.08

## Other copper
Bottom Layer:
  text "姓名：" at 7227.26,5141.22 h222.99
  text "学号：" at 7227.26,4771.22 h222.99

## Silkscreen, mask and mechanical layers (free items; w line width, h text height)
Top Overlay:
  lines w5.91: 5667.01,4825.08 5667.01,4915.08 5817.01,4915.08 5817.01,4825.08 5667.01,4825.08 ; 5667.01,4980.08 5667.01,5070.08 5817.01,5070.08 5817.01,4980.08 5667.01,4980.08 ; 5667.01,5135.08 5667.01,5225.08 5817.01,5225.08 5817.01,5135.08 5667.01,5135.08
  lines w10: 5087.01,5845.08 5087.01,5850.08 5117.01,5880.08 ; 5117.01,5775.08 5117.01,5880.08 ; 5147.01,5845.08 5147.01,5850.08 5117.01,5880.08 ; 5316.88,5117.08 5316.88,4935.21 5317.01,4935.08 ccw(c5434.4,4942.46) 5552.01,4940.08 5551.9,4940.18 5551.9,5124.46 ccw(c5434.51,5117.08) 5316.9,5119.46 ; 5352.01,5123.47 5352.01,4930.08 ; 5352.01,5125.08 cw(c5434.34,5117.13) 5517.01,5120.08 5517.03,4931.57 5517.14,4931.46 ; 5352.14,4941.46 5352.01,4930.08 ; 5517.01,4935.08 cw(c5434.34,4938.03) 5352.01,4930.08 ; 5272.01,5820.08 5272.01,5970.08 5277.01,5975.08 5792.01,5975.08 5792.01,5830.53 5792.46,5830.08 5512.01,5830.08 5512.01,5915.08 5437.01,5915.08 5437.01,5820.08 5272.01,5820.08 ; 5292.01,5300.08 5292.01,5420.08 5547.01,5420.08 5547.01,5300.08 5292.01,5300.08 ; 5542.01,5510.08 5542.01,5675.08 5792.01,5675.08 5792.01,5510.08 5542.01,5510.08 ; 5937.01,5250.08 5937.01,5420.08 6112.01,5420.08 6112.01,5250.08 5937.01,5250.08 ; 5957.01,4735.08 5957.01,5040.08 6062.01,5040.08 6062.01,4735.08 5957.01,4735.08 ; 6107.01,4720.08 6107.01,5025.08 6192.01,5025.08 6192.01,4720.08 6107.01,4720.08 ; 6122.01,5095.08 6122.01,5190.08 6412.01,5190.08 6412.01,5095.08 6122.01,5095.08 ; 6162.01,5510.08 6162.01,5970.08 6512.01,5970.08 6512.01,5855.08 6352.01,5855.08 6352.01,5510.08 6162.01,5510.08 ; 6187.01,5255.08 6472.01,5255.08 6472.01,5415.08 6187.01,5415.08 6187.01,5255.08 ; 6237.01,4640.08 6367.01,4640.08 6367.01,4600.08 6407.01,4600.08 6407.01,4685.08 6342.01,4685.08 6342.01,4740.08 6407.01,4740.08 6407.01,4785.08 6239.92,4785.08 6237.01,4782.17 6237.01,4640.08 ; 6277.01,4870.08 6277.01,5030.08 6442.01,5030.08 6442.01,4940.08 6392.01,4940.08 6392.01,4975.08 6357.01,4975.08 6357.01,4915.08 6447.01,4915.08 6447.01,4870.08 6277.01,4870.08 ; 6482.01,5510.08 6482.01,5620.08 6717.01,5620.08 6717.01,5510.08 6482.01,5510.08 ; 6484.92,4600.08 6612.01,4600.08 6612.01,4560.08 6652.01,4560.08 6652.01,4645.08 6592.01,4645.08 6592.01,4700.08 6652.01,4700.08 6652.01,4745.08 6484.92,4745.08 6484.92,4600.08 ; 6657.01,4840.08 6657.01,4960.08 6802.01,4960.08 6802.01,4800.08 6747.01,4800.08 6747.01,4875.08 6702.01,4875.08 6702.01,4840.08 6657.01,4840.08 ; 6657.01,5020.08 6657.01,5150.08 6827.01,5150.08 6827.01,5020.08 6657.01,5020.08 ; 6687.01,5050.08 6687.01,5120.08 6797.01,5120.08 6797.01,5050.08 6687.01,5050.08 ; 6712.01,4595.08 6842.01,4595.08 6842.01,4555.08 6882.01,4555.08 6882.01,4640.08 6822.01,4640.08 6822.01,4695.08 6882.01,4695.08 6882.01,4740.08 6714.92,4740.08 6712.01,4737.17 6712.01,4595.08 ; 6887.01,4985.08 6887.01,5145.08 7052.01,5145.08 7052.01,4985.08 6887.01,4985.08
  text "map" at 5866.1,6133.78 h127.76
  text "北" at 5056.49,5929.76 h133.8
  text "F3" at 6227.07,5908.66 h38.33
  text "F1" at 5315.42,5883.19 h38.33
  text "F2" at 5620.42,5883.19 h38.33
  text "E" at 6252.01,5733.05 h38.61
  text "D" at 5652.01,5578.05 h38.61
  text "C" at 6577.01,5548.05 h38.61
  text "G" at 5390.81,5343.52 h38.61
  text "B" at 6007.01,5318.05 h38.61
  text "A" at 6307.01,5313.05 h38.61
  text "L" at 6225.81,5123.52 h38.61
  text "H6" at 6709.22,5063.66 h38.33
  text "M" at 6952.01,5048.05 h38.61
  text "H1" at 6290.42,4928.19 h38.33
  text "H5" at 6695.42,4898.19 h38.33
  text "K" at 5992.01,4873.05 h38.61
  text "K" at 6137.01,4863.05 h38.61
  text "H2" at 6255.42,4693.19 h38.33
  text "H3" at 6509.22,4658.66 h38.33
  text "H4" at 6739.22,4648.66 h38.33
Bottom Overlay:
  lines w10: 4469.63,4256.81 4469.63,4422.8 ; 4510.46,4252.09 4510.46,4356.54 ; 4549.42,4251.26 4549.42,4355.71 ; 4590.04,4251.25 4590.04,4355.7 ; 4628.68,4251.42 4628.68,4355.86 ; 4666.54,4384.16 4667.21,4251.05 ; 4706.14,4253.09 4706.14,4357.53 ; 4745.1,4252.26 4745.1,4356.7 ; 4785.71,4252.25 4785.71,4356.69 ; 4824.36,4252.41 4824.36,4356.85 ; 4861.3,4259.61 4861.3,4425.6 ; 4903.56,4256.72 4903.56,4361.17 ; 4942.52,4255.89 4942.52,4360.34 ; 4983.14,4255.88 4983.14,4360.33 ; 5021.78,4256.05 5021.78,4360.49 ; 5060.65,4385.07 5061.32,4251.96 ; 5100.11,4253.87 5100.11,4358.31 ; 5139.07,4253.04 5139.07,4357.48 ; 5179.69,4253.03 5179.69,4357.47 ; 5218.33,4253.19 5218.33,4357.64 ; 5256.7,4254.01 5256.7,4420 ; 5296.52,4253.25 5296.52,4357.69 ; 5335.48,4252.42 5335.48,4356.86 ; 5376.1,4252.41 5376.1,4356.85 ; 5414.74,4252.57 5414.74,4357.01 ; 5454.12,4384.51 5454.79,4251.4 ; 5493.25,4252.69 5493.25,4357.14 ; 5532.21,4251.86 5532.21,4356.31 ; 5572.83,4251.85 5572.83,4356.3 ; 5611.47,4252.02 5611.47,4356.46 ; 5650.23,4257.74 5650.23,4423.73 ; 5690.45,4253.72 5690.45,4358.16 ; 5729.41,4252.89 5729.41,4357.34 ; 5770.03,4252.88 5770.03,4357.33 ; 5808.67,4253.04 5808.67,4357.49 ; 5847.58,4385.62 5848.25,4252.51 ; 5887.74,4255.38 5887.74,4359.82 ; 5926.7,4254.55 5926.7,4358.99 ; 5967.31,4254.54 5967.31,4358.98 ; 6005.96,4254.7 6005.96,4359.15 ; 6043.77,4255.88 6043.77,4421.87 ; 6083.92,4253.54 6083.92,4357.98 ; 6122.88,4252.71 6122.88,4357.15 ; 6163.49,4252.7 6163.49,4357.14 ; 6202.14,4252.86 6202.14,4357.31 ; 6241.41,4384.88 6242.09,4251.77 ; 6281.02,4253.17 6281.02,4357.61 ; 6319.98,4252.34 6319.98,4356.78 ; 6360.59,4252.33 6360.59,4356.77 ; 6399.24,4252.49 6399.24,4356.94 ; 6439.17,4257.74 6439.17,4423.73 ; 6478.37,4253.26 6478.37,4357.7 ; 6517.33,4252.43 6517.33,4356.88 ; 6557.95,4252.42 6557.95,4356.87 ; 6596.59,4252.58 6596.59,4357.03 ; 6635.27,4384.59 6635.94,4251.49 ; 6674.74,4252.52 6674.74,4356.97 ; 6713.69,4251.69 6713.69,4356.14 ; 6754.31,4251.68 6754.31,4356.13 ; 6792.95,4251.85 6792.95,4356.29 ; 6830.83,4255.88 6830.83,4421.87 ; 6871.71,4252.4 6871.71,4356.84 ; 6910.67,4251.57 6910.67,4356.02 ; 6951.29,4251.56 6951.29,4356.01 ; 6989.93,4251.72 6989.93,4356.17 ; 7029.1,4384.35 7029.78,4251.24 ; 7068.45,4253.87 7068.45,4358.32 ; 7107.41,4253.04 7107.41,4357.49 ; 7148.02,4253.03 7148.02,4357.48 ; 7186.66,4253.2 7186.66,4357.64 ; 7224.37,4255.88 7224.37,4421.87 ; 7265.55,4254.61 7265.55,4359.06 ; 7304.51,4253.78 7304.51,4358.23 ; 7345.12,4253.77 7345.12,4358.22 ; 7383.77,4253.93 7383.77,4358.38 ; 7422.63,4384.31 7423.3,4251.2 ; 7462.28,4253.87 7462.28,4358.32 ; 7501.24,4253.04 7501.24,4357.49 ; 7541.86,4253.03 7541.86,4357.48 ; 7580.5,4253.2 7580.5,4357.64 ; 7619.77,4250.28 7619.77,4416.27
Top Solder:
  lines w10: 5247.01,4795.08 5632.01,4795.08 5632.01,5265.08 5622.01,5265.08 ; 5477.01,5755.08 5877.01,5755.08 ; 6147.01,5450.08 6147.01,5215.08 6162.01,5215.08 ; 6212.01,4590.08 6212.01,4825.08 6497.01,4825.08 6497.01,5065.08 6087.01,5065.08 ; 6212.01,4830.08 6212.01,5065.08 ; 6417.01,5455.08 6417.01,5700.08 ; 6452.01,4550.08 6452.01,4820.08 ; 6452.01,4775.08 6902.01,4775.08 6902.01,4499.45 ; 6497.01,4980.08 6857.01,4980.08 ; 6497.01,5050.08 6497.01,5215.08 ; 6497.01,5066.22 6647.01,5065.08 ; 6497.01,5115.08 6647.01,5115.08 ; 6627.01,4975.08 6627.01,4777.58 6629.51,4775.08 ; 6687.01,4530.08 6687.01,4775.08 ; 6831.87,5089.94 6857.01,5089.94 ; 6857.01,4777.47 6857.01,4980.08 ; 6857.01,4910.08 7249.53,4910.08 7262,4897.61 ; 6857.01,5215.08 6857.01,4980.08 ; 6087.01,5065.08 6087.01,4605.08 6087.01,5065.08
  lines w15.75: 5232.01,5265.08 5852.01,5265.08 5857.01,5270.08 ; 5469.51,5462.58 5477.01,5470.08 5477.01,5875.08 ; 5857.01,5215.08 6512.01,5215.08 ; 5877.01,5455.08 5877.01,6010.08 ; 6114.51,5457.58 6122.01,5465.08 6122.01,6015.08 ; 6512.01,5445.08 6512.01,5215.08 ; 7102.3,5217.1 7100.27,5215.08 6512.01,5215.08
  lines w23.62: 5217.01,5460.08 7012.01,5455.08 ; 5232.01,6010.08 5237.01,4705.08 7292.01,4445.08 7317.01,4445.08 7331.45,4471.86 7322.01,4700.08 7262,4897.61 7102.3,5232.1 6902.01,5640.08 6658.23,6012.93 ; 5232.01,6015.08 6657.01,6015.08 ; 5852.01,5455.08 5857.01,4630.08 ; 5857.01,5230.08 5897.01,5230.08 ; 5877.01,4595.08 5877.01,4625.08 ; 5897.01,5455.08 5902.01,4625.08 ; 5952.01,6045.08 5954.51,6015.08
Bottom Solder:
  text "姓名：" at 7227.26,5141.22 h222.99
  text "学号：" at 7227.46,4771.4 h222.99
Mechanical 1:
  lines w10: 4356.93,4244.88 7727.01,4244.88 7727.01,6370.08 4356.93,6370.08 4356.93,4244.88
